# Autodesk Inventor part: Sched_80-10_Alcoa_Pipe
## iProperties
Shininess: 64.0
Length Units: 11272
Angle Units: 11279
Time Units: 11290
Mass Units: 11286
Length Display Precision: 3
Angle Display Precision: 2
Compacted: True
Part Number: Sched_80-10_Alcoa_Pipe
Document SubType Name: Modeling
Created: 2005-05
Designer: John Blackburn
Manufacturer: Standard
Standards Organization: Custom
Material: Aluminum-6061
Density: 0.0
Volumn: 0.0
Area: 0.0
PropertySet Name: Model Information
Control State: 0
Master: False
Checked Out: False
Author: John Blackburn
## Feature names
1. Extrusion1
